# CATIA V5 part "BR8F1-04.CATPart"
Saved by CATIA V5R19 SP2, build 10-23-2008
Part number: BR8F1-04
Definition: design
Nomenclature: BR8F1-04
Source: Unknown
Bounding box of the stored display mesh (mm): x -3.9 to 11.15, y 0 to 18.1, z 0 to 20.32
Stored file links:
  Z:\fausse table rondelle-20220905T211342Z-001\fausse table rondelle\BR8F1-04.CATPart
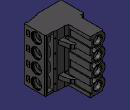
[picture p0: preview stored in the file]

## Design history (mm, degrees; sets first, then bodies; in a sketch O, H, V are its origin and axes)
AxisSystem1: origin (0, 0, 0), X (1, 0, 0), Y (0, 1, 0), Z (0, 0, 1)
Body1 "MANIFOLD_SOLID_BREP #59229" (main body)
  Solid1: solid without history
